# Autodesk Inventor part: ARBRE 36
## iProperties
Created: 2004-11
Part Number: ARBRE 36
Document SubType Name: Modeling
Designer: Bruno
Manufacturer: Standard
Standards Organization: Custom
Author: Bruno
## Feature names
1. Base1
